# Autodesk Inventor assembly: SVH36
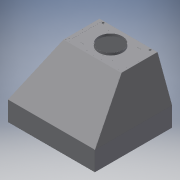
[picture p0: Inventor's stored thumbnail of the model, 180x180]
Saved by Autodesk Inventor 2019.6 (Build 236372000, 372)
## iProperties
Company: none
Created: 2025-04
Part Number: SVH36
Description: CATIA V5 STEP
Document SubType Name: Assembly
Designer: MMAK
Authority: none
Title: C:\Users\MMAK\Documents\SmarTeam\WEBSITE CAD\2025 TRADEWIND HOODS\SVH36.stp
Author: none
Revision Number: ANY
Sending System: CATIA V5 STEP AP203 v2
Preprocessor: CATIA Unofficial Packaging Version SP2
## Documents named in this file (8)
- C:\Users\MMAK\Documents\SmarTeam\WEBSITE CAD\2025 TRADEWIND HOODS\SVH36.iam
- C:\Users\MMAK\Documents\SmarTeam\WEBSITE CAD\2025 TRADEWIND HOODS\GU10_Socket_SUN-LITE.ipt
- C:\Users\MMAK\Documents\SmarTeam\WEBSITE CAD\2025 TRADEWIND HOODS\P72xx-xx-02 right end.ipt
- C:\Users\MMAK\Documents\SmarTeam\WEBSITE CAD\2025 TRADEWIND HOODS\P7236-12-01 back.ipt
- C:\Users\MMAK\Documents\SmarTeam\WEBSITE CAD\2025 TRADEWIND HOODS\P72xx-xx-03 left end.ipt
- C:\Users\MMAK\Documents\SmarTeam\WEBSITE CAD\2025 TRADEWIND HOODS\Blowers Mount Plate Rear.ipt
- C:\Users\MMAK\Documents\SmarTeam\WEBSITE CAD\2025 TRADEWIND HOODS\P7236-xx-07 face.ipt
- C:\Users\MMAK\Documents\SmarTeam\WEBSITE CAD\2025 TRADEWIND HOODS\Blower Mount Plate and Collar.iam
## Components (8 placed, 8 different names)
1. NAUO20
2. NAUO21
3. NAUO2
4. NAUO4
5. NAUO3
6. NAUO6
7. NAUO1
8. NAUO7 [sub-assembly]
